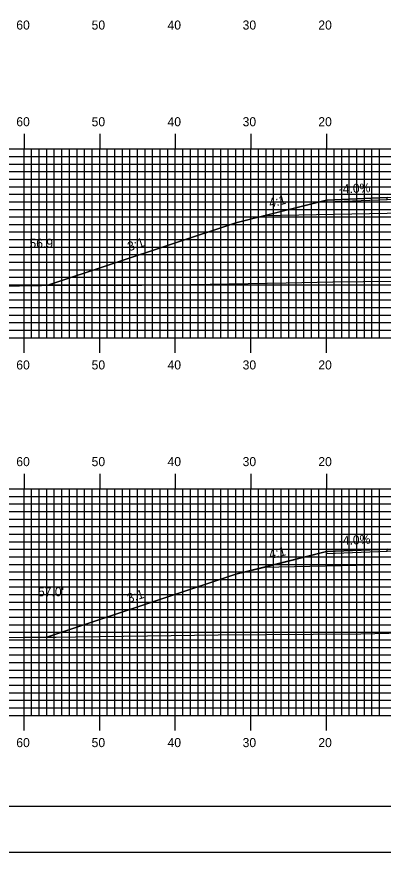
# Model space of a CAD drawing. Extents: x 1788156 to 1788500, y 442591 to 442811.
# Drawn here: x 1788261.2 to 1788309.6, y 442590.5 to 442701.2 of the extents above; entities that cross this region are included whole.
import ezdxf

# ---------------------------------------------------------------- set-up
doc = ezdxf.new("R2010")
doc.units = 0
for name, color, linetype in [('ANNOTATION', 7, 'Continuous'), ('BORDER', 7, 'Continuous'), ('D_Roadway_Centerline', 7, 'Continuous'), ('D_Roadway_Edge_Shoulder', 7, 'Continuous'), ('D_Roadway_SlopeLines', 7, 'Continuous'), ('D_Roadway_SubGrade', 7, 'Continuous'), ('D_Text_Standard', 7, 'Continuous'), ('H_V ANNOTATION', 7, 'Continuous'), ('MAJOR', 7, 'Continuous'), ('MINOR', 7, 'Continuous'), ('PLOT BOUNDARY', 7, 'Continuous'), ('S_Roadway_Centerline', 7, 'Continuous')]:
    doc.layers.add(name, color=color, linetype=linetype)

msp = doc.modelspace()

# ---------------------------------------------------------------- linework, layer by layer
at = {"layer": 'BORDER'}
msp.add_lwpolyline([(1788172.53, 442596.67), (1788492.53, 442596.67), (1788492.53, 442806.67), (1788172.53, 442806.67)], close=True, dxfattribs=at)
at = {"layer": 'D_Roadway_Centerline'}
for points in [[(1788265.27, 442665.61), (1788290.13, 442673.9), (1788293.77, 442674.81), (1788302.13, 442676.9), (1788310.13, 442677.22), (1788322.13, 442677.48), (1788334.13, 442677.75), (1788342.13, 442677.43), (1788350.49, 442675.33), (1788354.13, 442674.43), (1788374.61, 442667.6)], [(1788265.16, 442619.03), (1788290.13, 442627.36), (1788293.77, 442628.27), (1788302.13, 442630.36), (1788310.13, 442630.68), (1788322.13, 442630.94), (1788334.13, 442631.21), (1788342.13, 442630.89), (1788350.49, 442628.8), (1788354.13, 442627.89), (1788375.93, 442620.62)]]:
    msp.add_lwpolyline(points, dxfattribs=at)
at = {"layer": 'D_Roadway_Edge_Shoulder'}
for points in [[(1788310.13, 442677.22), (1788302.13, 442676.9), (1788302.13, 442676.65), (1788310.13, 442676.97)], [(1788310.13, 442630.68), (1788302.13, 442630.36), (1788302.13, 442630.11), (1788310.13, 442630.43)]]:
    msp.add_lwpolyline(points, close=True, dxfattribs=at)
at = {"layer": 'D_Roadway_SlopeLines'}
for points in [[(1788302.13, 442676.9), (1788290.13, 442673.9), (1788265.27, 442665.61)], [(1788302.13, 442630.36), (1788290.13, 442627.36), (1788265.16, 442619.03)]]:
    msp.add_lwpolyline(points, dxfattribs=at)
at = {"layer": 'D_Roadway_SubGrade'}
for points in [[(1788310.13, 442675.13), (1788293.77, 442674.81), (1788302.13, 442676.9), (1788302.13, 442676.65), (1788310.13, 442676.97), (1788322.13, 442677.23), (1788334.13, 442677.5), (1788342.13, 442677.18), (1788342.13, 442677.43), (1788350.49, 442675.33), (1788334.13, 442675.66), (1788322.13, 442675.4)], [(1788310.13, 442628.59), (1788293.77, 442628.27), (1788302.13, 442630.36), (1788302.13, 442630.11), (1788310.13, 442630.43), (1788322.13, 442630.69), (1788334.13, 442630.96), (1788342.13, 442630.64), (1788342.13, 442630.89), (1788350.49, 442628.8), (1788334.13, 442629.12), (1788322.13, 442628.86)]]:
    msp.add_lwpolyline(points, close=True, dxfattribs=at)
at = {"layer": 'MAJOR'}
for p, q in [((1788262.13, 442685.67), (1788262.13, 442683.67)), ((1788272.13, 442685.67), (1788272.13, 442683.67)), ((1788282.13, 442685.67), (1788282.13, 442683.67)), ((1788292.13, 442685.67), (1788292.13, 442683.67)), ((1788302.13, 442685.67), (1788302.13, 442683.67)), ((1788182.13, 442683.67), (1788462.13, 442683.67)), ((1788182.13, 442683.67), (1788462.13, 442683.67)), ((1788262.13, 442658.67), (1788262.13, 442683.67)), ((1788272.13, 442658.67), (1788272.13, 442683.67)), ((1788282.13, 442658.67), (1788282.13, 442683.67)), ((1788292.13, 442658.67), (1788292.13, 442683.67)), ((1788302.13, 442658.67), (1788302.13, 442683.67)), ((1788182.13, 442678.67), (1788462.13, 442678.67)), ((1788182.13, 442673.67), (1788462.13, 442673.67)), ((1788182.13, 442668.67), (1788462.13, 442668.67)), ((1788182.13, 442663.67), (1788462.13, 442663.67)), ((1788182.13, 442658.67), (1788462.13, 442658.67)), ((1788182.13, 442658.67), (1788462.13, 442658.67)), ((1788262.13, 442656.66), (1788262.13, 442658.67)), ((1788272.13, 442656.66), (1788272.13, 442658.67)), ((1788282.13, 442656.66), (1788282.13, 442658.67)), ((1788292.13, 442656.66), (1788292.13, 442658.67)), ((1788302.13, 442656.66), (1788302.13, 442658.67)), ((1788262.13, 442640.67), (1788262.13, 442638.67)), ((1788272.13, 442640.67), (1788272.13, 442638.67)), ((1788282.13, 442640.67), (1788282.13, 442638.67)), ((1788292.13, 442640.67), (1788292.13, 442638.67)), ((1788302.13, 442640.67), (1788302.13, 442638.67)), ((1788182.13, 442638.67), (1788462.13, 442638.67)), ((1788182.13, 442638.67), (1788462.13, 442638.67)), ((1788262.13, 442608.67), (1788262.13, 442638.67)), ((1788272.13, 442608.67), (1788272.13, 442638.67)), ((1788282.13, 442608.67), (1788282.13, 442638.67)), ((1788292.13, 442608.67), (1788292.13, 442638.67)), ((1788302.13, 442608.67), (1788302.13, 442638.67)), ((1788182.13, 442633.67), (1788462.13, 442633.67)), ((1788182.13, 442628.67), (1788462.13, 442628.67)), ((1788182.13, 442623.67), (1788462.13, 442623.67)), ((1788182.13, 442618.67), (1788462.13, 442618.67)), ((1788182.13, 442613.67), (1788462.13, 442613.67)), ((1788182.13, 442608.67), (1788462.13, 442608.67)), ((1788182.13, 442608.67), (1788462.13, 442608.67)), ((1788262.13, 442606.66), (1788262.13, 442608.67)), ((1788272.13, 442606.66), (1788272.13, 442608.67)), ((1788282.13, 442606.66), (1788282.13, 442608.67)), ((1788292.13, 442606.66), (1788292.13, 442608.67)), ((1788302.13, 442606.66), (1788302.13, 442608.67))]:
    msp.add_line(p, q, dxfattribs=at)
at = {"layer": 'MINOR'}
for p, q in [((1788263.13, 442658.67), (1788263.13, 442683.67)), ((1788264.13, 442658.67), (1788264.13, 442683.67)), ((1788265.13, 442658.67), (1788265.13, 442683.67)), ((1788266.13, 442658.67), (1788266.13, 442683.67)), ((1788267.13, 442658.67), (1788267.13, 442683.67)), ((1788268.13, 442658.67), (1788268.13, 442683.67)), ((1788269.13, 442658.67), (1788269.13, 442683.67)), ((1788270.13, 442658.67), (1788270.13, 442683.67)), ((1788271.13, 442658.67), (1788271.13, 442683.67)), ((1788273.13, 442658.67), (1788273.13, 442683.67)), ((1788274.13, 442658.67), (1788274.13, 442683.67)), ((1788275.13, 442658.67), (1788275.13, 442683.67)), ((1788276.13, 442658.67), (1788276.13, 442683.67)), ((1788277.13, 442658.67), (1788277.13, 442683.67)), ((1788278.13, 442658.67), (1788278.13, 442683.67)), ((1788279.13, 442658.67), (1788279.13, 442683.67)), ((1788280.13, 442658.67), (1788280.13, 442683.67)), ((1788281.13, 442658.67), (1788281.13, 442683.67)), ((1788283.13, 442658.67), (1788283.13, 442683.67)), ((1788284.13, 442658.67), (1788284.13, 442683.67)), ((1788285.13, 442658.67), (1788285.13, 442683.67)), ((1788286.13, 442658.67), (1788286.13, 442683.67)), ((1788287.13, 442658.67), (1788287.13, 442683.67)), ((1788288.13, 442658.67), (1788288.13, 442683.67)), ((1788289.13, 442658.67), (1788289.13, 442683.67)), ((1788290.13, 442658.67), (1788290.13, 442683.67)), ((1788291.13, 442658.67), (1788291.13, 442683.67)), ((1788293.13, 442658.67), (1788293.13, 442683.67)), ((1788294.13, 442658.67), (1788294.13, 442683.67)), ((1788295.13, 442658.67), (1788295.13, 442683.67)), ((1788296.13, 442658.67), (1788296.13, 442683.67)), ((1788297.13, 442658.67), (1788297.13, 442683.67)), ((1788298.13, 442658.67), (1788298.13, 442683.67)), ((1788299.13, 442658.67), (1788299.13, 442683.67)), ((1788300.13, 442658.67), (1788300.13, 442683.67)), ((1788301.13, 442658.67), (1788301.13, 442683.67)), ((1788303.13, 442658.67), (1788303.13, 442683.67)), ((1788304.13, 442658.67), (1788304.13, 442683.67)), ((1788305.13, 442658.67), (1788305.13, 442683.67)), ((1788306.13, 442658.67), (1788306.13, 442683.67)), ((1788307.13, 442658.67), (1788307.13, 442683.67)), ((1788308.13, 442658.67), (1788308.13, 442683.67)), ((1788309.13, 442658.67), (1788309.13, 442683.67)), ((1788182.13, 442682.67), (1788462.13, 442682.67)), ((1788182.13, 442681.67), (1788462.13, 442681.67)), ((1788182.13, 442680.67), (1788462.13, 442680.67)), ((1788182.13, 442679.67), (1788462.13, 442679.67)), ((1788182.13, 442677.67), (1788462.13, 442677.67)), ((1788182.13, 442676.67), (1788462.13, 442676.67)), ((1788182.13, 442675.67), (1788462.13, 442675.67)), ((1788182.13, 442674.67), (1788462.13, 442674.67)), ((1788182.13, 442672.67), (1788462.13, 442672.67)), ((1788182.13, 442671.67), (1788462.13, 442671.67)), ((1788182.13, 442670.67), (1788462.13, 442670.67)), ((1788182.13, 442669.67), (1788462.13, 442669.67)), ((1788182.13, 442667.67), (1788462.13, 442667.67)), ((1788182.13, 442666.67), (1788462.13, 442666.67)), ((1788182.13, 442665.67), (1788462.13, 442665.67)), ((1788182.13, 442664.67), (1788462.13, 442664.67)), ((1788182.13, 442662.67), (1788462.13, 442662.67)), ((1788182.13, 442661.67), (1788462.13, 442661.67)), ((1788182.13, 442660.67), (1788462.13, 442660.67)), ((1788182.13, 442659.67), (1788462.13, 442659.67)), ((1788263.13, 442608.67), (1788263.13, 442638.67)), ((1788264.13, 442608.67), (1788264.13, 442638.67)), ((1788265.13, 442608.67), (1788265.13, 442638.67)), ((1788266.13, 442608.67), (1788266.13, 442638.67)), ((1788267.13, 442608.67), (1788267.13, 442638.67)), ((1788268.13, 442608.67), (1788268.13, 442638.67)), ((1788269.13, 442608.67), (1788269.13, 442638.67)), ((1788270.13, 442608.67), (1788270.13, 442638.67)), ((1788271.13, 442608.67), (1788271.13, 442638.67)), ((1788273.13, 442608.67), (1788273.13, 442638.67)), ((1788274.13, 442608.67), (1788274.13, 442638.67)), ((1788275.13, 442608.67), (1788275.13, 442638.67)), ((1788276.13, 442608.67), (1788276.13, 442638.67)), ((1788277.13, 442608.67), (1788277.13, 442638.67)), ((1788278.13, 442608.67), (1788278.13, 442638.67)), ((1788279.13, 442608.67), (1788279.13, 442638.67)), ((1788280.13, 442608.67), (1788280.13, 442638.67)), ((1788281.13, 442608.67), (1788281.13, 442638.67)), ((1788283.13, 442608.67), (1788283.13, 442638.67)), ((1788284.13, 442608.67), (1788284.13, 442638.67)), ((1788285.13, 442608.67), (1788285.13, 442638.67)), ((1788286.13, 442608.67), (1788286.13, 442638.67)), ((1788287.13, 442608.67), (1788287.13, 442638.67)), ((1788288.13, 442608.67), (1788288.13, 442638.67)), ((1788289.13, 442608.67), (1788289.13, 442638.67)), ((1788290.13, 442608.67), (1788290.13, 442638.67)), ((1788291.13, 442608.67), (1788291.13, 442638.67)), ((1788293.13, 442608.67), (1788293.13, 442638.67)), ((1788294.13, 442608.67), (1788294.13, 442638.67)), ((1788295.13, 442608.67), (1788295.13, 442638.67)), ((1788296.13, 442608.67), (1788296.13, 442638.67)), ((1788297.13, 442608.67), (1788297.13, 442638.67)), ((1788298.13, 442608.67), (1788298.13, 442638.67)), ((1788299.13, 442608.67), (1788299.13, 442638.67)), ((1788300.13, 442608.67), (1788300.13, 442638.67)), ((1788301.13, 442608.67), (1788301.13, 442638.67)), ((1788303.13, 442608.67), (1788303.13, 442638.67)), ((1788304.13, 442608.67), (1788304.13, 442638.67)), ((1788305.13, 442608.67), (1788305.13, 442638.67)), ((1788306.13, 442608.67), (1788306.13, 442638.67)), ((1788307.13, 442608.67), (1788307.13, 442638.67)), ((1788308.13, 442608.67), (1788308.13, 442638.67)), ((1788309.13, 442608.67), (1788309.13, 442638.67)), ((1788182.13, 442637.67), (1788462.13, 442637.67)), ((1788182.13, 442636.67), (1788462.13, 442636.67)), ((1788182.13, 442635.67), (1788462.13, 442635.67)), ((1788182.13, 442634.67), (1788462.13, 442634.67)), ((1788182.13, 442632.67), (1788462.13, 442632.67)), ((1788182.13, 442631.67), (1788462.13, 442631.67)), ((1788182.13, 442630.67), (1788462.13, 442630.67)), ((1788182.13, 442629.67), (1788462.13, 442629.67)), ((1788182.13, 442627.67), (1788462.13, 442627.67)), ((1788182.13, 442626.67), (1788462.13, 442626.67)), ((1788182.13, 442625.67), (1788462.13, 442625.67)), ((1788182.13, 442624.67), (1788462.13, 442624.67)), ((1788182.13, 442622.67), (1788462.13, 442622.67)), ((1788182.13, 442621.67), (1788462.13, 442621.67)), ((1788182.13, 442620.67), (1788462.13, 442620.67)), ((1788182.13, 442619.67), (1788462.13, 442619.67)), ((1788182.13, 442617.67), (1788462.13, 442617.67)), ((1788182.13, 442616.67), (1788462.13, 442616.67)), ((1788182.13, 442615.67), (1788462.13, 442615.67)), ((1788182.13, 442614.67), (1788462.13, 442614.67)), ((1788182.13, 442612.67), (1788462.13, 442612.67)), ((1788182.13, 442611.67), (1788462.13, 442611.67)), ((1788182.13, 442610.67), (1788462.13, 442610.67)), ((1788182.13, 442609.67), (1788462.13, 442609.67))]:
    msp.add_line(p, q, dxfattribs=at)
at = {"layer": 'PLOT BOUNDARY'}
msp.add_lwpolyline([(1788156.34, 442590.55), (1788496.34, 442590.55), (1788496.34, 442810.55), (1788156.34, 442810.55)], close=True, dxfattribs=at)
at = {"layer": 'S_Roadway_Centerline'}
for points in [[(1788258.62, 442665.51), (1788267.31, 442665.64), (1788277.7, 442665.61), (1788281.73, 442665.66), (1788296.77, 442665.92), (1788302.97, 442666.05), (1788315, 442666.2), (1788315.2, 442666.2), (1788315.32, 442666.2), (1788327.17, 442666.51), (1788334.9, 442666.56), (1788347.04, 442666.73), (1788353.22, 442666.85), (1788363.21, 442667.18), (1788372.66, 442667.51), (1788379.02, 442667.79)], [(1788249.62, 442618.84), (1788262.21, 442619.01), (1788266.39, 442619.04), (1788268.95, 442619.09), (1788278.46, 442619.22), (1788287.81, 442619.35), (1788294.05, 442619.4), (1788306.66, 442619.47), (1788314.07, 442619.63), (1788326.15, 442619.87), (1788326.2, 442619.87), (1788326.24, 442619.87), (1788338.22, 442619.99), (1788345.23, 442620.17), (1788358.29, 442620.27), (1788364.21, 442620.32), (1788373.99, 442620.57), (1788383.47, 442620.81)]]:
    msp.add_lwpolyline(points, dxfattribs=at)

# ---------------------------------------------------------------- texts
at = {"layer": 'ANNOTATION'}
for s, rotation, p in [('-4.0%', 2.2906, (1788303.76, 442677.76)), ('4:1', 14.0362, (1788294.67, 442675.89)), ('3:1', 18.4348, (1788276.04, 442670.11)), ('-4.0%', 2.2906, (1788303.76, 442631.22)), ('4:1', 14.0362, (1788294.67, 442629.35)), ('3:1', 18.4348, (1788275.98, 442623.55))]:
    msp.add_text(s, height=1.2, rotation=rotation, dxfattribs=at).set_placement(p)
at = {"layer": 'D_Text_Standard'}
for s, p in [("56.9'", (1788262.84, 442670.58)), ("57.0'", (1788263.97, 442624.44))]:
    msp.add_text(s, height=1.2, dxfattribs=at).set_placement(p)
at = {"layer": 'H_V ANNOTATION'}
for s, p in [('60', (1788261.1, 442699.47)), ('50', (1788271.06, 442699.47)), ('40', (1788281.1, 442699.47)), ('30', (1788291.03, 442699.47)), ('20', (1788301.04, 442699.47)), ('60', (1788261.1, 442686.67)), ('50', (1788271.06, 442686.67)), ('40', (1788281.1, 442686.67)), ('30', (1788291.03, 442686.67)), ('20', (1788301.04, 442686.67)), ('60', (1788261.1, 442654.47)), ('50', (1788271.06, 442654.47)), ('40', (1788281.1, 442654.47)), ('30', (1788291.03, 442654.47)), ('20', (1788301.04, 442654.47)), ('60', (1788261.1, 442641.67)), ('50', (1788271.06, 442641.67)), ('40', (1788281.1, 442641.67)), ('30', (1788291.03, 442641.67)), ('20', (1788301.04, 442641.67)), ('60', (1788261.1, 442604.47)), ('50', (1788271.06, 442604.47)), ('40', (1788281.1, 442604.47)), ('30', (1788291.03, 442604.47)), ('20', (1788301.04, 442604.47))]:
    msp.add_text(s, height=1.2, dxfattribs=at).set_placement(p)

doc.saveas('drawing.dxf')
